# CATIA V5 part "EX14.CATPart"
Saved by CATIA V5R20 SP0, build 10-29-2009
Part number: EX14
Bounding box of the stored display mesh (mm): x -103.007 to 178.896, y -64.954 to 134.314, z 0 to 15
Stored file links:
  E:\Nouveau dossier\tarek\mécaniquee\Catia\TP 0\EX14.CATPart
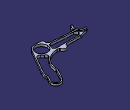
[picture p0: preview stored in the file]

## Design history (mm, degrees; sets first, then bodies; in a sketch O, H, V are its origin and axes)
Set1
  DatumSurface1 to DatumSurface54
Body1 (main body)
